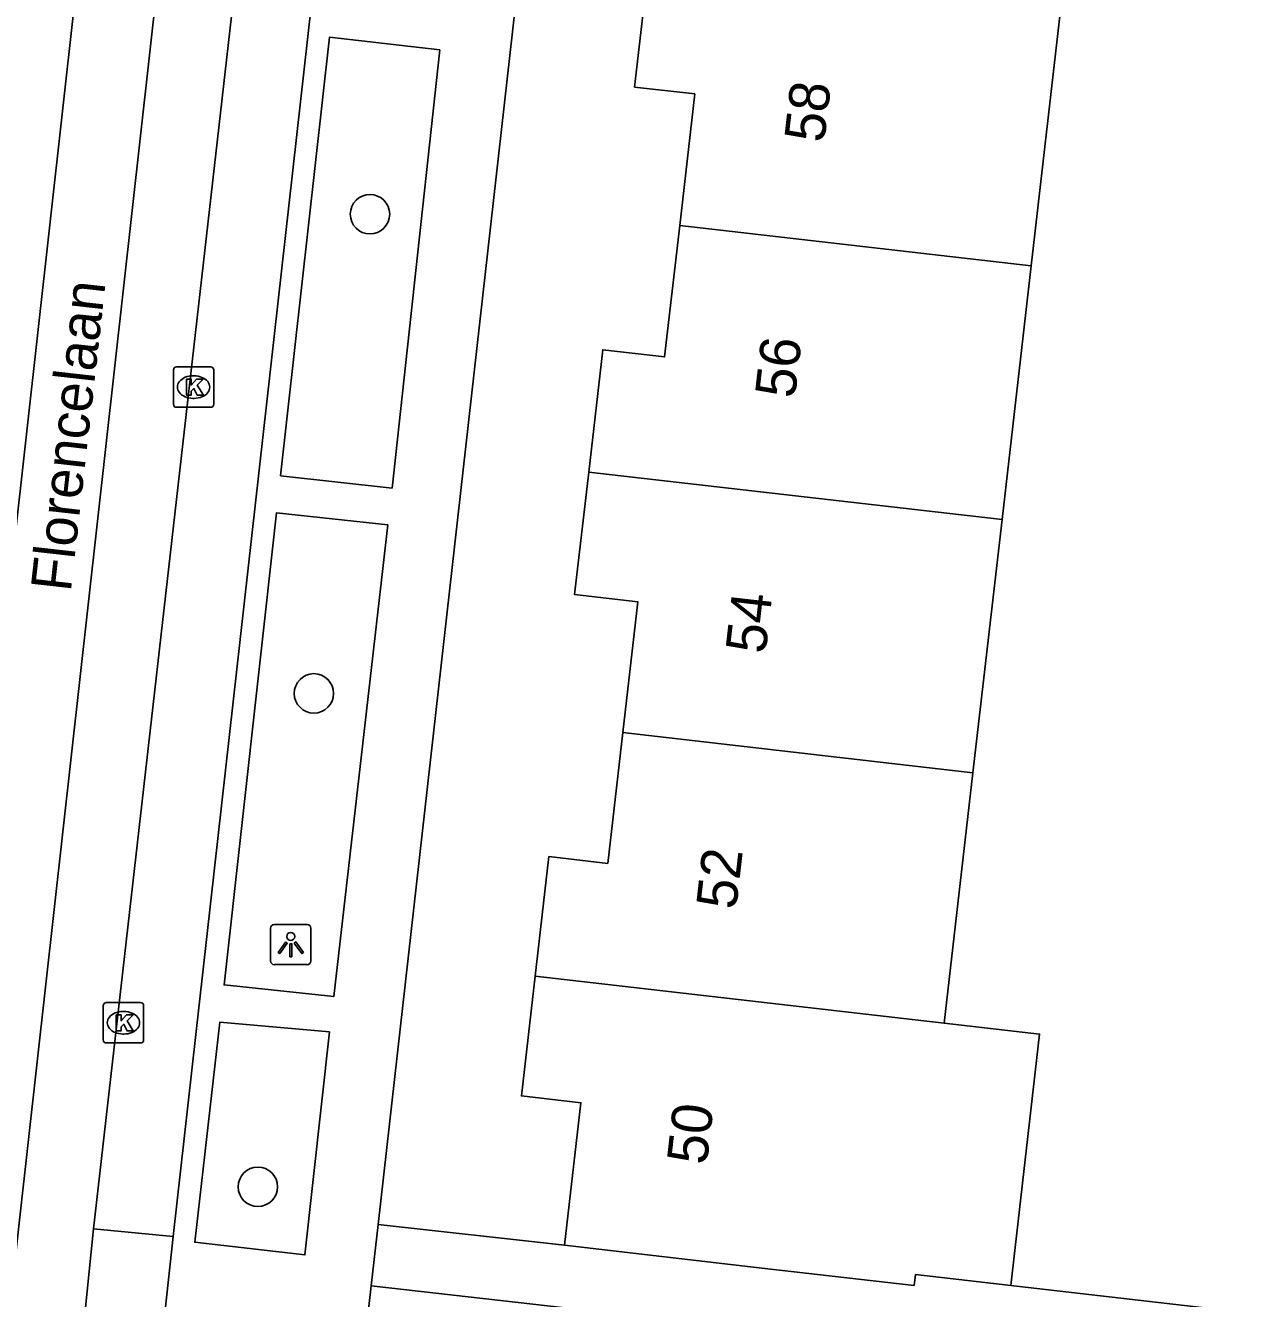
# Model space of a CAD drawing. Extents: x 162082 to 163393, y 388091 to 388632.
# Drawn here: x 162731.21 to 162761.37, y 388507.04 to 388538.63 of the extents above; entities that cross this region are included whole.
import ezdxf

# ---------------------------------------------------------------- set-up
doc = ezdxf.new("R2010")
doc.units = 0
for name, color, linetype in [('IMGEO_Boom', 7, 'Continuous'), ('IMGEO_Kolk', 7, 'Continuous'), ('IMGEO_Lichtpunt', 7, 'Continuous'), ('IMGEO_Openbare_ruimte_label', 7, 'Continuous'), ('IMGEO_Pand', 7, 'Continuous'), ('IMGEO_Pand_nummerreeks', 7, 'Continuous'), ('IMGEO_Rijbaan_lokaal_gesloten', 7, 'Continuous'), ('IMGEO_Rijbaan_lokaal_open', 7, 'Continuous'), ('IMGEO_Voetpad_open', 7, 'Continuous')]:
    doc.layers.add(name, color=color, linetype=linetype)

msp = doc.modelspace()

# ---------------------------------------------------------------- linework, layer by layer
at = {"layer": 'IMGEO_Boom'}
for centre in [(162739.754, 388533.943), (162738.364, 388522.057), (162736.974, 388509.816)]:
    msp.add_circle(centre, 0.489, dxfattribs=at)
at = {"layer": 'IMGEO_Kolk'}
for p, q in [((162734.878, 388529.229), (162734.878, 388530.081)), ((162734.953, 388530.155), (162735.805, 388530.155)), ((162735.879, 388530.081), (162735.879, 388529.229)), ((162735.366, 388529.935), (162735.391, 388529.935)), ((162735.389, 388529.375), (162735.364, 388529.375)), ((162735.805, 388529.155), (162734.953, 388529.155)), ((162733.138, 388513.459), (162733.138, 388514.311)), ((162733.213, 388514.385), (162734.065, 388514.385)), ((162734.139, 388514.311), (162734.139, 388513.459)), ((162733.626, 388514.165), (162733.651, 388514.165)), ((162733.649, 388513.605), (162733.624, 388513.605)), ((162734.065, 388513.385), (162733.213, 388513.385))]:
    msp.add_line(p, q, dxfattribs=at)
for points in [[(162734.878, 388529.229), (162734.878, 388530.081)], [(162734.953, 388530.155), (162735.805, 388530.155)], [(162735.879, 388530.081), (162735.879, 388529.229)], [(162735.199, 388529.855), (162735.322, 388529.855), (162735.322, 388529.704), (162735.452, 388529.855), (162735.616, 388529.855), (162735.47, 388529.704), (162735.623, 388529.455), (162735.471, 388529.455), (162735.386, 388529.619), (162735.322, 388529.552), (162735.322, 388529.455), (162735.199, 388529.455), (162735.199, 388529.855)], [(162735.805, 388529.155), (162734.953, 388529.155)], [(162733.138, 388513.459), (162733.138, 388514.311)], [(162733.213, 388514.385), (162734.065, 388514.385)], [(162734.139, 388514.311), (162734.139, 388513.459)], [(162733.459, 388514.085), (162733.582, 388514.085), (162733.582, 388513.934), (162733.712, 388514.085), (162733.876, 388514.085), (162733.73, 388513.934), (162733.883, 388513.685), (162733.731, 388513.685), (162733.646, 388513.849), (162733.582, 388513.782), (162733.582, 388513.685), (162733.459, 388513.685), (162733.459, 388514.085)], [(162734.065, 388513.385), (162733.213, 388513.385)]]:
    msp.add_lwpolyline(points, dxfattribs=at)
for centre, start, end in [((162734.955, 388530.079), 91.552, 178.448), ((162734.955, 388530.079), 91.552, 178.448), ((162735.803, 388530.079), 1.552, 88.448), ((162735.803, 388530.079), 1.552, 88.448), ((162734.955, 388529.231), 181.552, 268.448), ((162734.955, 388529.231), 181.552, 268.448), ((162735.803, 388529.231), 271.552, 358.448), ((162735.803, 388529.231), 271.552, 358.448), ((162733.215, 388514.309), 91.552, 178.448), ((162733.215, 388514.309), 91.552, 178.448), ((162734.063, 388514.309), 1.552, 88.448), ((162734.063, 388514.309), 1.552, 88.448), ((162733.215, 388513.461), 181.552, 268.448), ((162733.215, 388513.461), 181.552, 268.448), ((162734.063, 388513.461), 271.552, 358.448), ((162734.063, 388513.461), 271.552, 358.448)]:
    msp.add_arc(centre, 0.0765, start, end, dxfattribs=at)
for centre, major_axis, ratio, start_param, end_param in [((162735.365, 388529.655), (-0.387, 0.002), 0.722429, 4.712389, 7.853982), ((162735.39, 388529.655), (-0.39, 0.002), 0.717154, 1.570796, 4.712389), ((162733.625, 388513.885), (-0.387, 0.002), 0.722429, 4.712389, 7.853982), ((162733.65, 388513.885), (-0.39, 0.002), 0.717154, 1.570796, 4.712389)]:
    msp.add_ellipse(centre, major_axis=major_axis, ratio=ratio, start_param=start_param, end_param=end_param, dxfattribs=at)
at = {"layer": 'IMGEO_Lichtpunt'}
for p, q in [((162737.29, 388516.228), (162737.29, 388515.421)), ((162737.29, 388516.228), (162737.29, 388515.421)), ((162738.192, 388516.323), (162737.384, 388516.323)), ((162738.192, 388516.323), (162737.384, 388516.323)), ((162738.286, 388515.421), (162738.286, 388516.228)), ((162738.286, 388515.421), (162738.286, 388516.228)), ((162737.384, 388515.327), (162738.192, 388515.327)), ((162737.384, 388515.327), (162738.192, 388515.327))]:
    msp.add_line(p, q, dxfattribs=at)
for points in [[(162737.664, 388515.892), (162737.703, 388515.864), (162737.515, 388515.602), (162737.477, 388515.629), (162737.664, 388515.892)], [(162737.766, 388515.844), (162737.813, 388515.844), (162737.813, 388515.522), (162737.766, 388515.522), (162737.766, 388515.844)], [(162737.876, 388515.864), (162737.914, 388515.891), (162738.101, 388515.629), (162738.062, 388515.601), (162737.876, 388515.864)]]:
    msp.add_lwpolyline(points, dxfattribs=at)
msp.add_circle((162737.789, 388516.026), 0.0994, dxfattribs=at)
for centre, start, end in [((162737.384, 388516.228), 90, 180), ((162737.384, 388516.228), 90, 180), ((162738.192, 388516.228), 0, 90), ((162738.192, 388516.228), 0, 90), ((162737.384, 388515.421), 180, 270), ((162737.384, 388515.421), 180, 270), ((162738.192, 388515.421), 270, 0), ((162738.192, 388515.421), 270, 360)]:
    msp.add_arc(centre, 0.0946, start, end, dxfattribs=at)
at = {"layer": 'IMGEO_Pand'}
for points in [[(162747.436, 388533.665), (162747.811, 388536.927), (162746.316, 388537.099), (162746.661, 388540.105)], [(162756.873, 388538.933), (162756.154, 388532.665)], [(162745.179, 388527.545), (162745.527, 388530.58), (162747.062, 388530.403), (162747.436, 388533.665)], [(162756.154, 388532.665), (162747.436, 388533.665)], [(162756.154, 388532.665), (162755.431, 388526.368)], [(162746.024, 388521.085), (162746.396, 388524.33), (162744.83, 388524.509), (162745.179, 388527.545)], [(162745.179, 388527.545), (162755.431, 388526.368)], [(162755.431, 388526.368), (162754.711, 388520.088)], [(162743.851, 388515.038), (162744.192, 388518.007), (162745.652, 388517.839), (162746.024, 388521.085)], [(162754.711, 388520.088), (162746.024, 388521.085)], [(162754.711, 388520.088), (162753.998, 388513.874)], [(162744.578, 388508.364), (162744.984, 388511.902), (162743.511, 388512.071), (162743.851, 388515.038)], [(162743.851, 388515.038), (162753.998, 388513.874)], [(162753.998, 388513.874), (162756.364, 388513.603), (162755.649, 388507.365)], [(162755.649, 388507.365), (162753.282, 388507.637), (162753.251, 388507.368), (162749.546, 388507.793), (162744.578, 388508.364)]]:
    msp.add_lwpolyline(points, dxfattribs=at)
at = {"layer": 'IMGEO_Rijbaan_lokaal_gesloten'}
for points in [[(162728.711, 388523.165), (162730.61, 388522.925), (162734.225, 388555.356), (162732.326, 388555.585)], [(162738.143, 388554.92), (162736.204, 388555.092), (162728.485, 388485.946), (162730.347, 388485.702)], [(162738.143, 388554.92), (162732.894, 388508.771)], [(162732.894, 388508.771), (162732.479, 388504.706)]]:
    msp.add_lwpolyline(points, dxfattribs=at)
at = {"layer": 'IMGEO_Rijbaan_lokaal_open'}
for points in [[(162734.876, 388508.583), (162732.894, 388508.771)], [(162734.876, 388508.583), (162734.427, 388504.473)]]:
    msp.add_lwpolyline(points, dxfattribs=at)
at = {"layer": 'IMGEO_Voetpad_open'}
for points in [[(162739.957, 388508.884), (162745.878, 388561.46)], [(162739.881, 388553.247), (162734.876, 388508.583)], [(162741.489, 388538.023), (162740.301, 388527.149), (162737.538, 388527.456), (162738.747, 388538.334), (162741.489, 388538.023)], [(162740.194, 388526.236), (162738.86, 388514.54), (162736.136, 388514.826), (162737.436, 388526.539), (162740.194, 388526.236)], [(162738.748, 388513.664), (162738.139, 388508.128), (162735.408, 388508.44), (162736.03, 388513.903), (162738.748, 388513.664)], [(162739.785, 388507.361), (162739.957, 388508.884)], [(162739.957, 388508.884), (162744.578, 388508.364)], [(162755.649, 388507.365), (162764.19, 388506.386), (162764.321, 388507.898)], [(162737.36, 388485.969), (162739.785, 388507.361)], [(162744.595, 388506.815), (162739.785, 388507.361)]]:
    msp.add_lwpolyline(points, dxfattribs=at)

# ---------------------------------------------------------------- texts
at = {"layer": 'IMGEO_Openbare_ruimte_label'}
msp.add_text('Florencelaan', height=1, rotation=83.5713, dxfattribs=at).set_placement((162732.331, 388524.556))
at = {"layer": 'IMGEO_Pand_nummerreeks'}
for s, rotation, p in [('58', 83.4445, (162751.02, 388535.699)), ('56', 83.4445, (162750.292, 388529.357)), ('54', 83.4445, (162749.563, 388523.017)), ('52', 83.4445, (162748.834, 388516.675)), ('50', 83.4456, (162748.107, 388510.342))]:
    msp.add_text(s, height=1, rotation=rotation, dxfattribs=at).set_placement(p)

doc.saveas('drawing.dxf')
